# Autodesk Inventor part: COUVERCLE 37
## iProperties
Created: 2004-11
Part Number: COUVERCLE 37
Document SubType Name: Modeling
Designer: Bruno
Manufacturer: Standard
Standards Organization: Custom
Author: Bruno
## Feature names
1. Base1
